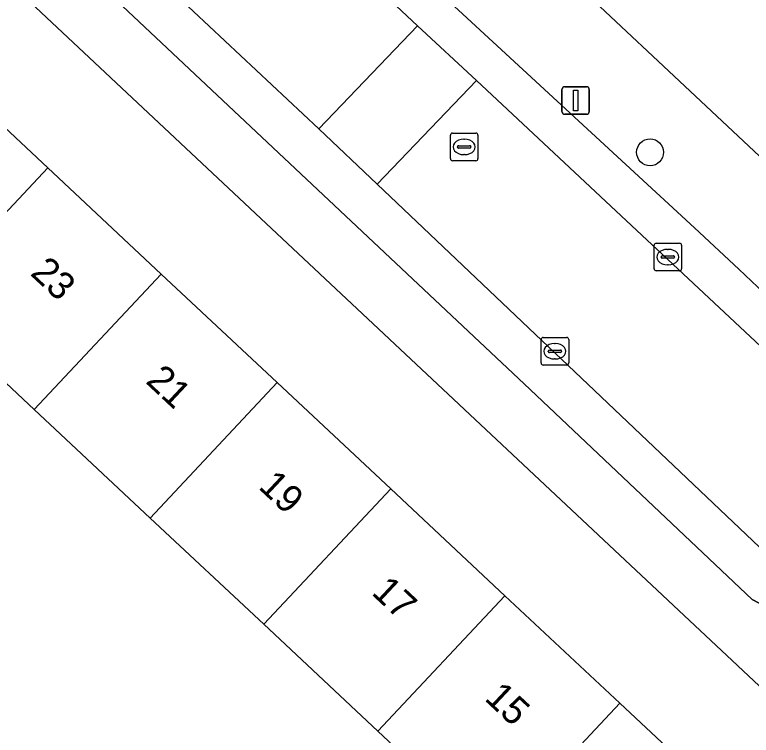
# Model space of a CAD drawing. Extents: x 159039 to 160102, y 381214 to 382524.
# Drawn here: x 159360.87 to 159387.61, y 381595.72 to 381621.89 of the extents above; entities that cross this region are included whole.
import ezdxf

# ---------------------------------------------------------------- set-up
doc = ezdxf.new("R2010")
doc.units = 0
for name, color, linetype in [('IMGEO_Boom', 7, 'Continuous'), ('IMGEO_Erf', 7, 'Continuous'), ('IMGEO_Kolk', 7, 'Continuous'), ('IMGEO_Lichtmast', 7, 'Continuous'), ('IMGEO_Pand', 7, 'Continuous'), ('IMGEO_Pand_nummerreeks', 7, 'Continuous'), ('IMGEO_Parkeervlak_open', 7, 'Continuous'), ('IMGEO_Rijbaan_lokaal_open', 7, 'Continuous'), ('IMGEO_Rioolput', 7, 'Continuous'), ('IMGEO_Voetpad_open', 7, 'Continuous')]:
    doc.layers.add(name, color=color, linetype=linetype)

msp = doc.modelspace()

# ---------------------------------------------------------------- linework, layer by layer
at = {"layer": 'IMGEO_Boom'}
msp.add_circle((159383.94, 381616.897), 0.489, dxfattribs=at)
at = {"layer": 'IMGEO_Erf'}
for points in [[(159389.318, 381638.402), (159383.506, 381643.834), (159376.297, 381636.12), (159356.349, 381654.764), (159352.158, 381650.279), (159395.631, 381609.52)], [(159394.275, 381590.729), (159394.004, 381591.525), (159393.542, 381592.228), (159342.745, 381639.886)], [(159358.121, 381620.029), (159362.065, 381616.336), (159366.187, 381612.475), (159370.397, 381608.534), (159374.52, 381604.672), (159378.667, 381600.788), (159382.839, 381596.881), (159386.831, 381593.143), (159379.941, 381585.785), (159375.948, 381589.524), (159378.229, 381591.959), (159374.057, 381595.866), (159369.91, 381599.75), (159365.786, 381603.611), (159361.577, 381607.553), (159357.455, 381611.414)]]:
    msp.add_lwpolyline(points, dxfattribs=at)
at = {"layer": 'IMGEO_Kolk'}
for p, q in [((159384.159, 381613.591), (159385.011, 381613.591)), ((159384.084, 381612.665), (159384.084, 381613.517)), ((159384.572, 381613.371), (159384.597, 381613.371)), ((159385.085, 381613.517), (159385.085, 381612.665)), ((159384.343, 381613.085), (159384.343, 381613.097)), ((159384.781, 381613.048), (159384.383, 381613.048)), ((159384.386, 381613.134), (159384.784, 381613.134)), ((159384.827, 381613.097), (159384.827, 381613.085)), ((159384.595, 381612.811), (159384.57, 381612.811)), ((159385.011, 381612.591), (159384.159, 381612.591)), ((159379.982, 381609.243), (159379.982, 381610.095)), ((159380.057, 381610.169), (159380.909, 381610.169)), ((159380.983, 381610.095), (159380.983, 381609.243)), ((159380.47, 381609.949), (159380.495, 381609.949)), ((159380.241, 381609.663), (159380.241, 381609.675)), ((159380.679, 381609.626), (159380.281, 381609.626)), ((159380.284, 381609.712), (159380.682, 381609.712)), ((159380.725, 381609.675), (159380.725, 381609.663)), ((159380.493, 381609.389), (159380.468, 381609.389)), ((159380.909, 381609.169), (159380.057, 381609.169))]:
    msp.add_line(p, q, dxfattribs=at)
for points in [[(159384.159, 381613.591), (159385.011, 381613.591)], [(159384.084, 381612.665), (159384.084, 381613.517)], [(159385.085, 381613.517), (159385.085, 381612.665)], [(159385.011, 381612.591), (159384.159, 381612.591)], [(159379.982, 381609.243), (159379.982, 381610.095)], [(159380.057, 381610.169), (159380.909, 381610.169)], [(159380.983, 381610.095), (159380.983, 381609.243)], [(159380.909, 381609.169), (159380.057, 381609.169)]]:
    msp.add_lwpolyline(points, dxfattribs=at)
for centre, radius, start, end in [((159384.161, 381613.515), 0.0765, 91.552, 178.448), ((159384.161, 381613.515), 0.0765, 91.552, 178.448), ((159385.009, 381613.515), 0.0765, 1.552, 88.448), ((159385.009, 381613.515), 0.0765, 1.552, 88.448), ((159384.383, 381613.094), 0.0403, 85.8775, 175.7526), ((159384.38, 381613.084), 0.0366, 178.938, 274.7102), ((159384.784, 381613.091), 0.043, 264.8664, 352.4533), ((159384.788, 381613.096), 0.0386, 1.7309, 96.639), ((159384.161, 381612.667), 0.0765, 181.552, 268.448), ((159384.161, 381612.667), 0.0765, 181.552, 268.448), ((159385.009, 381612.667), 0.0765, 271.552, 358.448), ((159385.009, 381612.667), 0.0765, 271.552, 358.448), ((159380.059, 381610.093), 0.0765, 91.552, 178.448), ((159380.059, 381610.093), 0.0765, 91.552, 178.448), ((159380.907, 381610.093), 0.0765, 1.552, 88.448), ((159380.907, 381610.093), 0.0765, 1.552, 88.448), ((159380.281, 381609.672), 0.0403, 85.8775, 175.7526), ((159380.278, 381609.662), 0.0366, 178.938, 274.7102), ((159380.682, 381609.669), 0.043, 264.8664, 352.4533), ((159380.686, 381609.674), 0.0386, 1.7309, 96.639), ((159380.059, 381609.245), 0.0765, 181.552, 268.448), ((159380.059, 381609.245), 0.0765, 181.552, 268.448), ((159380.907, 381609.245), 0.0765, 271.552, 358.448), ((159380.907, 381609.245), 0.0765, 271.552, 358.448)]:
    msp.add_arc(centre, radius, start, end, dxfattribs=at)
for centre, major_axis, ratio, start_param, end_param in [((159384.571, 381613.091), (-0.387, 0.002), 0.722429, 4.712389, 7.853982), ((159384.596, 381613.091), (-0.39, 0.002), 0.717154, 1.570796, 4.712389), ((159380.469, 381609.669), (-0.387, 0.002), 0.722429, 4.712389, 7.853982), ((159380.494, 381609.669), (-0.39, 0.002), 0.717154, 1.570796, 4.712389)]:
    msp.add_ellipse(centre, major_axis=major_axis, ratio=ratio, start_param=start_param, end_param=end_param, dxfattribs=at)
at = {"layer": 'IMGEO_Lichtmast'}
for p, q in [((159380.74, 381618.379), (159380.74, 381619.179)), ((159380.74, 381619.179), (159380.74, 381618.379)), ((159380.84, 381619.279), (159381.63, 381619.279)), ((159381.63, 381619.279), (159380.84, 381619.279)), ((159381.73, 381619.179), (159381.73, 381618.379)), ((159381.73, 381618.379), (159381.73, 381619.179)), ((159381.63, 381618.279), (159380.84, 381618.279)), ((159380.84, 381618.279), (159381.63, 381618.279))]:
    msp.add_line(p, q, dxfattribs=at)
msp.add_lwpolyline([(159381.16, 381619.154), (159381.31, 381619.154), (159381.31, 381618.404), (159381.16, 381618.404), (159381.16, 381619.154)], dxfattribs=at)
for centre, start, end in [((159380.84, 381619.179), 90, 180), ((159380.84, 381619.179), 90, 180), ((159381.63, 381619.179), 0, 90), ((159381.63, 381619.179), 360, 90), ((159380.84, 381618.379), 180, 270), ((159380.84, 381618.379), 180, 270), ((159381.63, 381618.379), 270, 0), ((159381.63, 381618.379), 270, 0)]:
    msp.add_arc(centre, 0.1, start, end, dxfattribs=at)
at = {"layer": 'IMGEO_Pand'}
for points in [[(159362.065, 381616.336), (159358.121, 381620.029), (159358.002, 381620.153), (159353.392, 381615.231), (159353.511, 381615.107), (159357.455, 381611.414)], [(159366.187, 381612.475), (159362.065, 381616.336), (159357.455, 381611.414), (159361.577, 381607.553)], [(159366.187, 381612.475), (159361.577, 381607.553), (159365.786, 381603.611), (159370.397, 381608.534)], [(159369.91, 381599.75), (159374.52, 381604.672), (159370.397, 381608.534), (159365.786, 381603.611)], [(159369.91, 381599.75), (159374.057, 381595.866), (159378.667, 381600.788), (159374.52, 381604.672)], [(159378.667, 381600.788), (159374.057, 381595.866), (159378.229, 381591.959), (159382.839, 381596.881)], [(159382.839, 381596.881), (159378.229, 381591.959), (159375.948, 381589.524), (159379.941, 381585.785), (159386.831, 381593.143)]]:
    msp.add_lwpolyline(points, close=True, dxfattribs=at)
at = {"layer": 'IMGEO_Parkeervlak_open'}
for points in [[(159350.551, 381646.369), (159349.592, 381646.114), (159349.163, 381646.192), (159375.49, 381621.485), (159377.636, 381619.505), (159391.899, 381606.165)], [(159391.528, 381608.516), (159387.16, 381612.657), (159385.548, 381614.156), (159371.994, 381626.67), (159370.318, 381628.217), (159369.445, 381629.023), (159353.302, 381644.347), (159351.297, 381646.185)], [(159390.534, 381600.059), (159374.034, 381615.743), (159371.908, 381617.745), (159345.733, 381642.263)], [(159346.061, 381639.72), (159347.779, 381638.103), (159364.373, 381622.606), (159379.367, 381608.486), (159387.648, 381600.646), (159388.157, 381600.38), (159388.347, 381600.349), (159390.052, 381600.247)]]:
    msp.add_lwpolyline(points, dxfattribs=at)
at = {"layer": 'IMGEO_Rijbaan_lokaal_open'}
for points in [[(159349.163, 381646.192), (159349.078, 381646.27), (159347.311, 381647.955), (159347.221, 381648.04), (159328.37, 381665.744), (159324.865, 381661.853), (159343.743, 381644.17), (159343.882, 381644.04), (159345.494, 381642.49), (159345.733, 381642.263), (159371.908, 381617.745), (159375.49, 381621.485)], [(159375.49, 381621.485), (159371.908, 381617.745), (159374.034, 381615.743), (159377.636, 381619.505)]]:
    msp.add_lwpolyline(points, close=True, dxfattribs=at)
for points in [[(159377.636, 381619.505), (159374.034, 381615.743), (159390.534, 381600.059)], [(159390.78, 381599.828), (159396.104, 381594.741), (159396.201, 381594.694), (159396.752, 381594.079), (159400.56, 381598.009), (159399.295, 381599.22), (159395.41, 381602.868), (159392.347, 381605.744), (159391.899, 381606.165), (159377.636, 381619.505)]]:
    msp.add_lwpolyline(points, dxfattribs=at)
at = {"layer": 'IMGEO_Rioolput'}
for p, q in [((159376.762, 381617.592), (159377.614, 381617.592)), ((159376.687, 381616.666), (159376.687, 381617.518)), ((159377.175, 381617.372), (159377.2, 381617.372)), ((159377.688, 381617.518), (159377.688, 381616.666)), ((159376.946, 381617.086), (159376.946, 381617.098)), ((159377.384, 381617.049), (159376.986, 381617.049)), ((159376.989, 381617.135), (159377.387, 381617.135)), ((159377.43, 381617.098), (159377.43, 381617.086)), ((159377.198, 381616.812), (159377.173, 381616.812)), ((159377.614, 381616.592), (159376.762, 381616.592))]:
    msp.add_line(p, q, dxfattribs=at)
for points in [[(159376.762, 381617.592), (159377.614, 381617.592)], [(159376.687, 381616.666), (159376.687, 381617.518)], [(159377.688, 381617.518), (159377.688, 381616.666)], [(159377.614, 381616.592), (159376.762, 381616.592)]]:
    msp.add_lwpolyline(points, dxfattribs=at)
for centre, radius, start, end in [((159376.764, 381617.516), 0.0765, 91.552, 178.448), ((159376.764, 381617.516), 0.0765, 91.552, 178.448), ((159377.612, 381617.516), 0.0765, 1.552, 88.448), ((159377.612, 381617.516), 0.0765, 1.552, 88.448), ((159376.986, 381617.095), 0.0403, 85.8775, 175.7526), ((159376.983, 381617.085), 0.0366, 178.938, 274.7102), ((159377.387, 381617.092), 0.043, 264.8664, 352.4533), ((159377.391, 381617.097), 0.0386, 1.7309, 96.639), ((159376.764, 381616.668), 0.0765, 181.552, 268.448), ((159376.764, 381616.668), 0.0765, 181.552, 268.448), ((159377.612, 381616.668), 0.0765, 271.552, 358.448), ((159377.612, 381616.668), 0.0765, 271.552, 358.448)]:
    msp.add_arc(centre, radius, start, end, dxfattribs=at)
for centre, major_axis, ratio, start_param, end_param in [((159377.174, 381617.092), (-0.387, 0.002), 0.722429, 4.712389, 7.853982), ((159377.199, 381617.092), (-0.39, 0.002), 0.717154, 1.570796, 4.712389)]:
    msp.add_ellipse(centre, major_axis=major_axis, ratio=ratio, start_param=start_param, end_param=end_param, dxfattribs=at)
at = {"layer": 'IMGEO_Voetpad_open'}
for points in [[(159302.886, 381680.595), (159301.466, 381678.598), (159308.878, 381671.662), (159309.873, 381670.73), (159341.159, 381641.45), (159342.745, 381639.886), (159393.542, 381592.228), (159394.004, 381591.525), (159396.752, 381594.079), (159396.201, 381594.694), (159396.104, 381594.741)], [(159405.269, 381601.074), (159402.729, 381603.248), (159399.489, 381606.141), (159395.631, 381609.52), (159352.158, 381650.279), (159356.349, 381654.764), (159370.466, 381669.868), (159369.241, 381671.05), (159361.907, 381663.275), (159352.232, 381653.017), (159350.825, 381651.526), (159337.645, 381663.865)], [(159351.297, 381646.185), (159353.302, 381644.347), (159369.445, 381629.023), (159370.318, 381628.217), (159371.994, 381626.67), (159385.548, 381614.156), (159387.16, 381612.657), (159391.528, 381608.516)], [(159390.052, 381600.247), (159388.347, 381600.349), (159388.157, 381600.38), (159387.648, 381600.646), (159379.367, 381608.486), (159364.373, 381622.606), (159347.779, 381638.103), (159346.061, 381639.72)]]:
    msp.add_lwpolyline(points, dxfattribs=at)

# ---------------------------------------------------------------- texts
at = {"layer": 'IMGEO_Pand_nummerreeks'}
for s, p in [('23', (159361.4, 381612.465)), ('21', (159365.59, 381608.542)), ('19', (159369.68, 381604.711)), ('17', (159373.787, 381600.865)), ('15', (159377.893, 381597.02))]:
    msp.add_text(s, height=1, rotation=316.8786, dxfattribs=at).set_placement(p)

doc.saveas('drawing.dxf')
